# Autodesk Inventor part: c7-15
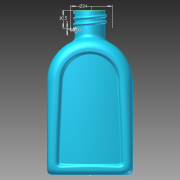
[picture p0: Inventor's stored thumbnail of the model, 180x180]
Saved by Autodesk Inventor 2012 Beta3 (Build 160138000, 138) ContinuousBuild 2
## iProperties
Created: 2010-12
Part Number: c7-15
Material: Default
Document SubType Name: Modeling
Designer: Beta-8540w
Density: 1 g/cm^3
Author: Beta-8540w
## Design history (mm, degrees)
sketch "Sketch1"
  geometry: L1 (-25, 0)-(25, 0); L2 (25, 0)-(25, 80); L3 (25, 80)-(-25, 80); L4 (-25, 80)-(-25, 0); 2 further points
  constraints: 8 end point, 2 parallel, 1 coincident, 1 horizontal, 1 midpoint, 1 perpendicular
  dimensions: "d0" = 50 distance of L3.end L2.end; "d1" = 80 distance of L2.end L1.end
extrude "Extrusion1" new body sketch "Sketch1" distance "d2" = 15; taper "d3" = 0 deg
feature "FaceDraft1" dims angle "d4" = -2 deg
fillet "Fillet1"
fillet "Fillet2" dims "d5" = 8, "d6" = 8, "d7" = 8, "d8" = 8, "d9" = 8, "d10" = 8, "d11" = 3, "d12" = 3, "d13" = 3, "d14" = 6, "d15" = 5
sketch "Sketch2"
  geometry: L1 (5.522, 12)-(38.474, 12) reference; L2 (0, 0)-(43.996, 0) reference; L3 (41.757, 6.83)-(41.995, 0); L4 (41.925, 2)-(2.071, 2); L5 (2.001, 0)-(2.24, 6.83); L6 (5.522, 10)-(38.474, 10); A1 r 5.284 centre (38.474, 6.716) between (43.755, 6.9) and (38.474, 12) reference; A2 r 5.284 centre (5.522, 6.716) between (5.522, 12) and (0.241, 6.9) reference; A3 r 3.284 centre (38.474, 6.716) between (41.757, 6.83) and (38.474, 10); A4 r 3.284 centre (5.522, 6.716) between (5.522, 10) and (2.24, 6.83); 1 further point
  constraints: 8 end point, 4 point on circle, 4 point on line, 2 centre point, 1 other
  dimensions: "d16" = 2 radial gap between concentric circles of A2 A4
extrude "Extrusion2" cut sketch "Sketch2" distance "d17" = 1; taper "d18" = 0 deg
feature "FaceDraft2" dims angle "d19" = 15 deg
sketch "Sketch3" dims "d20" = 2.5
  geometry: L1 (16.476, 3)-(-16.476, 3) reference; L2 (16.476, 5.5)-(-16.476, 5.5); 9 further points
  constraints: 2 end point, 2 parallel, 1 horizontal alignment, 19 other
extrude "Extrusion3" cut sketch "Sketch3" distance "d21" = 3; taper "d22" = 0 deg
feature "FaceDraft3" dims angle "d23" = 10 deg
workplane "Work Plane1"
sketch "Sketch4"
  geometry: L1 (41.1, -1.222)-(41.476, -12) reference; L2 (41.476, -12)-(-8.524, -12) reference; L3 (-8.524, -12)-(-8.147, -1.222) reference; L4 (-3.776, 3)-(-1.272, 3) reference; L5 (-0.743, 0)-(33.695, 0) reference; L6 (34.225, 3)-(36.728, 3) reference; L7 (-11.024, -1.856)-(43.976, -1.856); A1 r 100 centre (16.476, -98) between (43.976, -1.856) and (-11.024, -1.856); 2 further points
  constraints: 2 end point, 2 point on circle, 1 centre point, 1 midpoint, 1 parallel, 1 vertical alignment, 4 other
  dimensions: "d25" = 100 radius of A1; "d26" = 14 distance edge to line of A1 L2; "d27" = 55 distance of L7.start L7.end
extrude_surface "ExtrusionSrf1" sketch "Sketch4" dims "d28" = 86, "d29" = 0
feature "Replace Face1"
fillet "Fillet3" dims "d34" = 1, "d35" = 2
mirror "Mirror1"
fillet "Fillet4" dims "d36" = 20
workplane "Work Plane3"
sketch "Sketch6"
  geometry: C1 r 9 at (0, 0); 1 further point
  constraints: 1 centre point, 1 coincident
  dimensions: "d38" = 18 diameter of C1
extrude "Top Boss" join sketch "Sketch6" distance "d39" = 16; taper "d40" = 0 deg
fillet "Fillet5" dims "d41" = 3
shell "Shell1" dims "d62" = 1
sketch "Sketch7"
  geometry: L1 (-9, 80.285)-(-9, 96) reference; C1 r 1 at (-9, 94.5); 1 further point
  constraints: 1 centre point, 1 point on line
  dimensions: "d42" = 1.5 distance of L1.end C1.centre; "d43" = 2 diameter of C1
coil "Coil2" sketch "Sketch7" pitch "d52" = 10; turns "d54" = 2; dims "d53" = 7, "d55" = 0, angle "d56" = 90 deg, angle "d57" = 90 deg, "d58" = 0, "d59" = 0
fillet "Fillet6" dims "d60" = 0.9
fillet "Fillet7" dims "d61" = 0.2
sketch "Sketch8"
  geometry: L1 (-9.664, 85.5)-(-11.164, 85.5); L2 (-11.164, 85.5)-(-11.164, 84.5); L3 (-11.164, 84.5)-(-9.664, 83.954); L4 (-9.664, 83.954)-(-9.664, 85.5); L5 (0.836, 2.555)-(0.836, 98.256); L6 (-9, 96)-(9, 96) reference; 1 further point
  constraints: 10 end point, 2 parallel, 1 horizontal, 1 perpendicular
  dimensions: "d63" = 1 distance of L1.end L2.end; "d64" = 20 deg angle of L1 L3; "d65" = 10.5 distance between parallel lines of L6 L1; "d66" = 24 diameter of L2 L5; "d67" = 1.5 distance of L1.start L1.end
fillet "Fillet8"
body "Solid1"
body "Srf1"
node "Project Cut Edges1"
